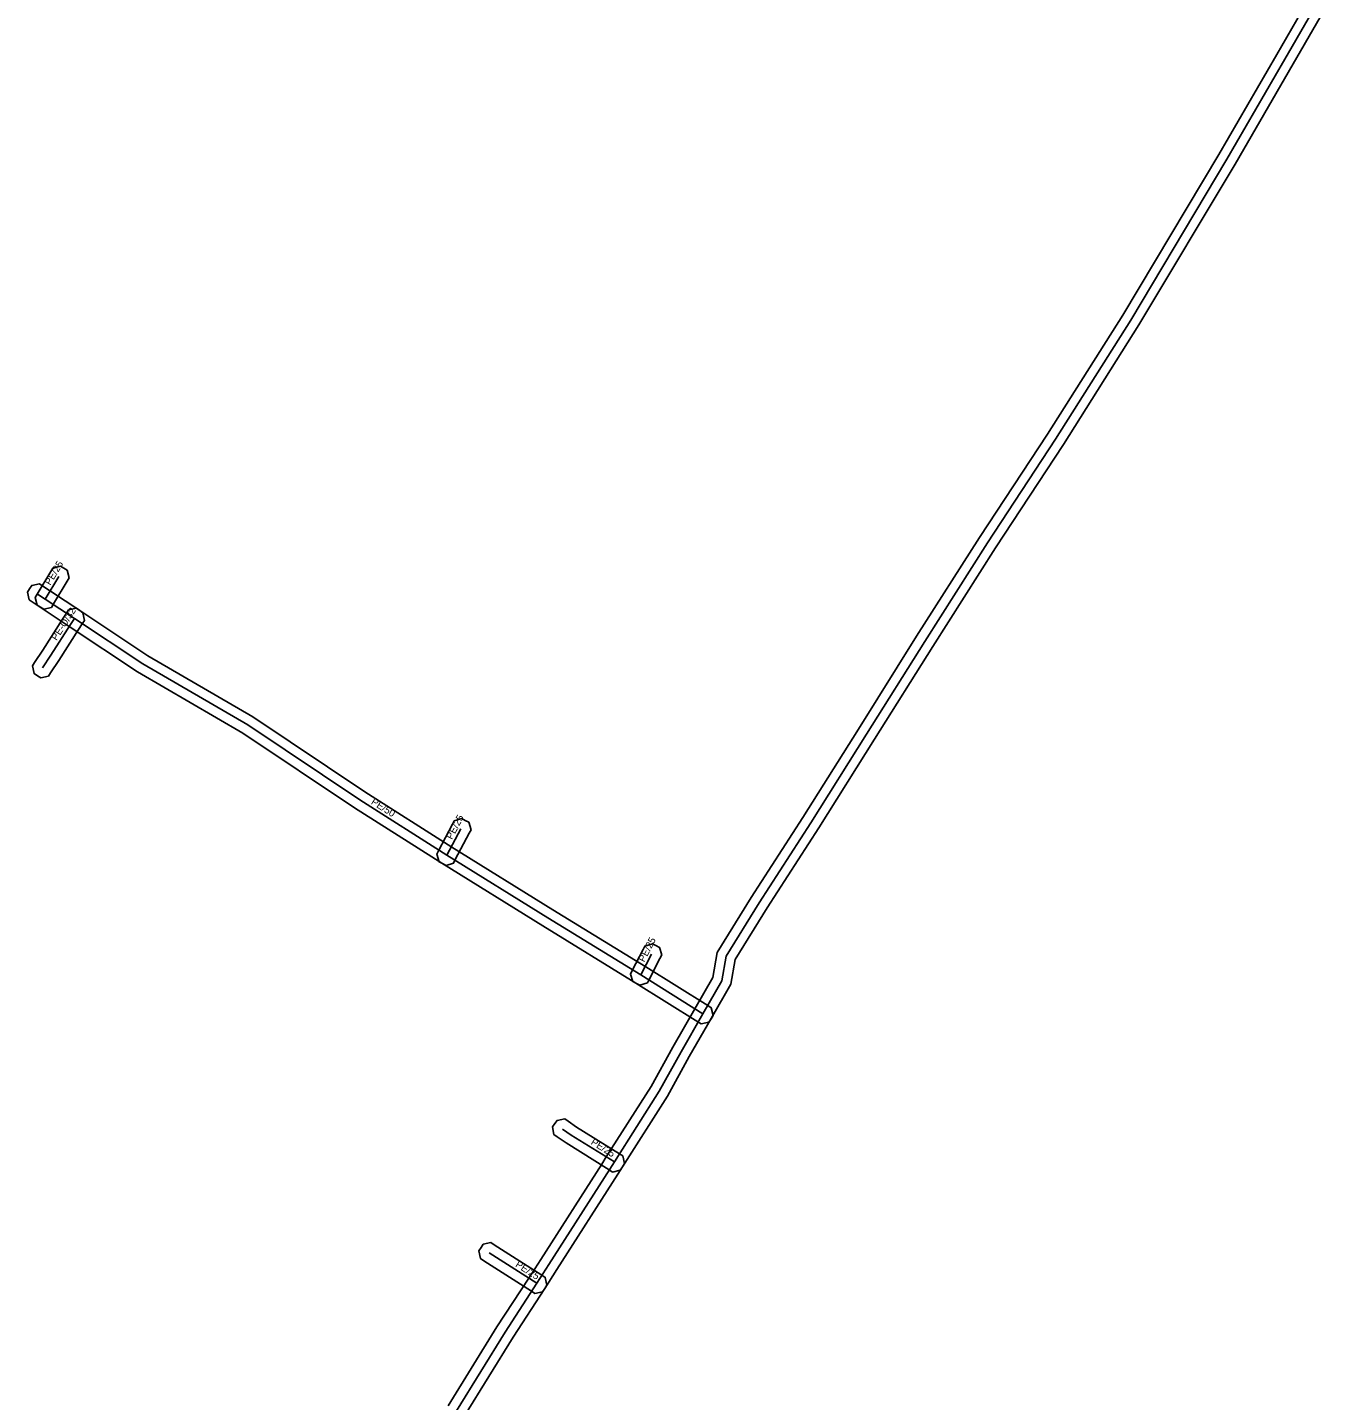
# Model space of a CAD drawing. Extents: x -681131 to -680872, y -1058347 to -1057759.
# Drawn here: x -681119.4 to -680980.7, y -1058053 to -1057908.3 of the extents above; entities that cross this region are included whole.
import ezdxf

# ---------------------------------------------------------------- set-up
doc = ezdxf.new("R2010")
doc.units = 0
for name, color, linetype in [('1', 7, 'Continuous'), ('24', 7, 'Continuous'), ('30', 7, 'Continuous')]:
    doc.layers.add(name, color=color, linetype=linetype)

msp = doc.modelspace()

# ---------------------------------------------------------------- linework, layer by layer
at = {"layer": '1'}
for points in [[(-681075.01, -1058053.6), (-681069.88, -1058045.28), (-681066.53, -1058040.14), (-681065.24, -1058038.16), (-681058.83, -1058028.11), (-681058.36, -1058027.36), (-681053.64, -1058019.94), (-681051.35, -1058015.8), (-681049.04, -1058011.77), (-681047.14, -1058008.47), (-681046.68, -1058005.83), (-681043.09, -1058000.04), (-681037.64, -1057991.6), (-681031.78, -1057982.29), (-681025.65, -1057972.5), (-681019.01, -1057962.1), (-681011.85, -1057951.19), (-681003.93, -1057938.65), (-680993.8, -1057921.71), (-680987.7, -1057911.18), (-680982.42, -1057902.02)], [(-680980.66, -1057902.96), (-680985.96, -1057912.18), (-680992.08, -1057922.73), (-681002.23, -1057939.69), (-681010.17, -1057952.27), (-681017.33, -1057963.18), (-681023.95, -1057973.56), (-681030.08, -1057983.35), (-681035.96, -1057992.68), (-681041.41, -1058001.11), (-681044.78, -1058006.55), (-681045.22, -1058009.15), (-681047.3, -1058012.77), (-681049.61, -1058016.78), (-681051.92, -1058020.96), (-681056.66, -1058028.42), (-681057.14, -1058029.17), (-681063.56, -1058039.24), (-681064.85, -1058041.23), (-681068.19, -1058046.35), (-681073.31, -1058054.66)]]:
    msp.add_lwpolyline(points, dxfattribs=at)
for points in [[(-681114.97, -1057966.34), (-681115.18, -1057966.69), (-681116.62, -1057969.09), (-681116.84, -1057969.45), (-681117.64, -1057969.65), (-681117.99, -1057969.44), (-681118.35, -1057969.22), (-681118.55, -1057968.42), (-681118.34, -1057968.07), (-681116.9, -1057965.67), (-681116.68, -1057965.31), (-681115.88, -1057965.11), (-681115.53, -1057965.32), (-681115.17, -1057965.54)], [(-681048.35, -1058013.34), (-681048.7, -1058013.12), (-681055.26, -1058009.04), (-681065.06, -1058003.01), (-681075.68, -1057996.41), (-681084.9, -1057990.56), (-681096.67, -1057982.69), (-681107.75, -1057976.25), (-681114.97, -1057971.45), (-681118.03, -1057969.41), (-681118.85, -1057968.88), (-681119.2, -1057968.65), (-681119.36, -1057967.84), (-681119.14, -1057967.49), (-681118.91, -1057967.14), (-681118.1, -1057966.98), (-681117.75, -1057967.21), (-681116.93, -1057967.75), (-681113.86, -1057969.78), (-681106.69, -1057974.55), (-681095.61, -1057980.99), (-681083.8, -1057988.88), (-681074.62, -1057994.71), (-681064, -1058001.31), (-681054.2, -1058007.34), (-681047.64, -1058011.42), (-681047.29, -1058011.64), (-681047.1, -1058012.45), (-681047.32, -1058012.8), (-681047.54, -1058013.15)], [(-681118.84, -1057975.61), (-681118.61, -1057975.27), (-681117.75, -1057973.95), (-681115.67, -1057970.69), (-681115.25, -1057970.06), (-681115.02, -1057969.72), (-681114.21, -1057969.55), (-681113.86, -1057969.78), (-681113.52, -1057970.01), (-681113.35, -1057970.83), (-681113.58, -1057971.17), (-681113.99, -1057971.79), (-681116.07, -1057975.03), (-681116.93, -1057976.36), (-681117.16, -1057976.71), (-681117.97, -1057976.88), (-681118.32, -1057976.65), (-681118.67, -1057976.43)], [(-681072.61, -1057992.88), (-681072.81, -1057993.25), (-681074.27, -1057996.02), (-681074.46, -1057996.39), (-681075.25, -1057996.64), (-681075.61, -1057996.45), (-681075.98, -1057996.25), (-681076.23, -1057995.46), (-681076.04, -1057995.09), (-681074.58, -1057992.31), (-681074.38, -1057991.95), (-681073.59, -1057991.7), (-681073.22, -1057991.9), (-681072.86, -1057992.09)], [(-681052.51, -1058006.07), (-681052.7, -1058006.44), (-681053.84, -1058008.65), (-681054.03, -1058009.02), (-681054.82, -1058009.27), (-681055.19, -1058009.08), (-681055.56, -1058008.89), (-681055.81, -1058008.1), (-681055.62, -1058007.73), (-681054.48, -1058005.52), (-681054.29, -1058005.15), (-681053.5, -1058004.9), (-681053.13, -1058005.09), (-681052.76, -1058005.28)], [(-681057.69, -1058028.96), (-681058.04, -1058028.74), (-681062.6, -1058025.89), (-681063.54, -1058025.24), (-681063.87, -1058025), (-681064.02, -1058024.18), (-681063.78, -1058023.84), (-681063.54, -1058023.51), (-681062.72, -1058023.36), (-681062.39, -1058023.6), (-681061.5, -1058024.23), (-681056.98, -1058027.04), (-681056.63, -1058027.26), (-681056.44, -1058028.07), (-681056.66, -1058028.42), (-681056.88, -1058028.77)], [(-681065.88, -1058041.75), (-681066.23, -1058041.52), (-681071.25, -1058038.3), (-681071.6, -1058038.08), (-681071.78, -1058037.27), (-681071.55, -1058036.92), (-681071.33, -1058036.57), (-681070.52, -1058036.39), (-681070.17, -1058036.62), (-681065.15, -1058039.84), (-681064.8, -1058040.06), (-681064.62, -1058040.87), (-681064.85, -1058041.22), (-681065.07, -1058041.57)]]:
    msp.add_lwpolyline(points, close=True, dxfattribs=at)
at = {"layer": '24'}
for points in [[(-680981.54, -1057902.49), (-680986.83, -1057911.68), (-680992.94, -1057922.22), (-681003.08, -1057939.17), (-681011.01, -1057951.73), (-681018.17, -1057962.64), (-681024.8, -1057973.03), (-681030.93, -1057982.82), (-681036.8, -1057992.14), (-681042.25, -1058000.58), (-681045.73, -1058006.19), (-681046.18, -1058008.81), (-681048.17, -1058012.27), (-681050.48, -1058016.29), (-681052.78, -1058020.45), (-681057.51, -1058027.89), (-681057.98, -1058028.64), (-681064.4, -1058038.7), (-681065.69, -1058040.68), (-681069.03, -1058045.82), (-681074.16, -1058054.13)], [(-681116.04, -1057966.18), (-681117.48, -1057968.58)], [(-681048.17, -1058012.27), (-681054.73, -1058008.19), (-681064.53, -1058002.16), (-681075.15, -1057995.56), (-681084.35, -1057989.72), (-681096.14, -1057981.84), (-681107.22, -1057975.4), (-681114.42, -1057970.62), (-681117.48, -1057968.58), (-681118.3, -1057968.04)], [(-681117.77, -1057975.81), (-681116.91, -1057974.49), (-681114.83, -1057971.24), (-681114.42, -1057970.62)], [(-681073.69, -1057992.78), (-681075.15, -1057995.56)], [(-681053.59, -1058005.98), (-681054.73, -1058008.19)], [(-681057.51, -1058027.89), (-681062.05, -1058025.06), (-681062.96, -1058024.42)], [(-681065.69, -1058040.68), (-681070.71, -1058037.46)]]:
    msp.add_lwpolyline(points, dxfattribs=at)

# ---------------------------------------------------------------- texts
at = {"layer": '30'}
for s, rotation, p in [('PE/25', 59.0362, (-681116.96, -1057967.18)), ('PE-O/32', 57.3808, (-681116.29, -1057973.01)), ('PE/50', 327.5933, (-681083.21, -1057990.12)), ('PE/25', 62.2924, (-681074.62, -1057993.97)), ('PE/25', 62.7136, (-681054.36, -1058006.89)), ('PE/25', 328.0627, (-681060.05, -1058025.98)), ('PE/25', 327.3225, (-681068, -1058038.87))]:
    msp.add_text(s, height=0.75, rotation=rotation, dxfattribs=at).set_placement(p)

doc.saveas('drawing.dxf')
